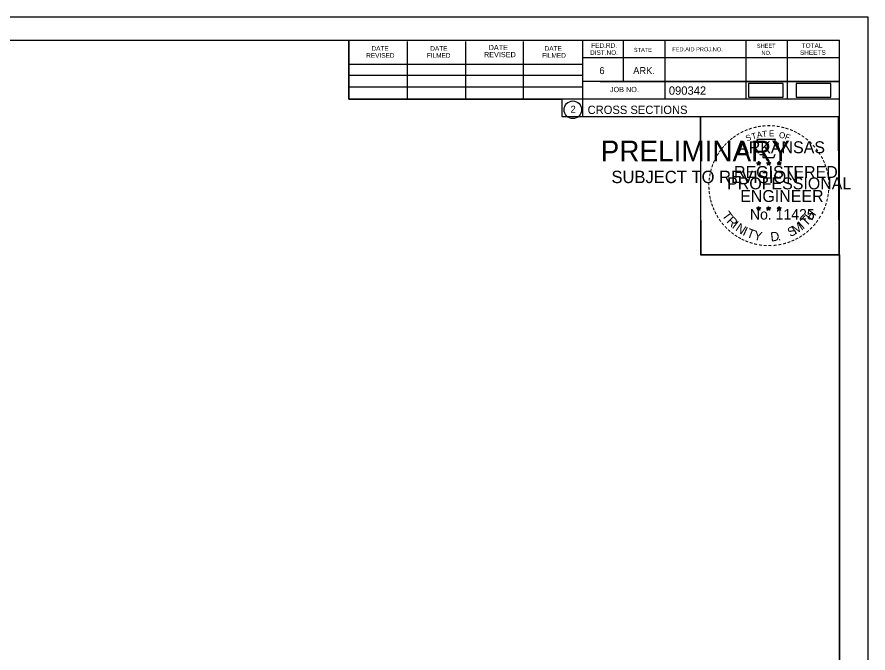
# Model space of a CAD drawing. Extents: x 1370515 to 1370849, y 383299 to 386073.
# Drawn here: x 1370706.1 to 1370848.7, y 385112.8 to 385219.5 of the extents above; entities that cross this region are included whole.
import ezdxf

# ---------------------------------------------------------------- set-up
doc = ezdxf.new("R2010")
doc.units = 0
for name, color, linetype in [('R_Border', 7, 'Continuous'), ('R_Border PE', 7, 'Continuous'), ('R_Border Prem', 7, 'Continuous'), ('R_Detour', 7, 'Continuous'), ('R_No Plot', 7, 'Continuous')]:
    doc.layers.add(name, color=color, linetype=linetype)

msp = doc.modelspace()

# ---------------------------------------------------------------- linework, layer by layer
at = {"layer": 'R_Border'}
for p, q in [((1370527.8, 385215.57), (1370843.98, 385215.57)), ((1370761.72, 385205.69), (1370761.72, 385215.57)), ((1370800.88, 385215.57), (1370800.88, 385202.77)), ((1370807.72, 385215.57), (1370807.72, 385208.63)), ((1370814.66, 385215.57), (1370814.66, 385205.69)), ((1370828.24, 385215.57), (1370828.24, 385205.69)), ((1370835.18, 385215.57), (1370835.18, 385205.69)), ((1370843.98, 385010.11), (1370843.98, 385215.57)), ((1370771.58, 385205.69), (1370771.58, 385215.37)), ((1370781.34, 385205.69), (1370781.34, 385215.37)), ((1370791.02, 385205.69), (1370791.02, 385215.37)), ((1370843.98, 385212.63), (1370800.88, 385212.63)), ((1370843.98, 385212.65), (1370843.98, 385212.65)), ((1370761.72, 385211.55), (1370800.88, 385211.55)), ((1370761.72, 385209.69), (1370800.88, 385209.69)), ((1370843.98, 385208.63), (1370800.88, 385208.63)), ((1370803.84, 385208.63), (1370843.98, 385208.63)), ((1370761.72, 385205.69), (1370761.72, 385207.75)), ((1370761.72, 385207.75), (1370800.88, 385207.75)), ((1370843.98, 385205.69), (1370761.72, 385205.69)), ((1370800.88, 385202.77), (1370843.98, 385202.77))]:
    msp.add_line(p, q, dxfattribs=at)
msp.add_circle((1370799.27, 385203.91), 1.47, dxfattribs=at)
at = {"layer": 'R_Border PE'}
for p, q in [((1370830.07, 385195.03), (1370830.42, 385194.92)), ((1370830.07, 385195.03), (1370830.32, 385194.98)), ((1370830.07, 385195.03), (1370830.3, 385194.91)), ((1370830.2, 385194.62), (1370830.42, 385194.92)), ((1370830.2, 385194.62), (1370830.33, 385194.86)), ((1370830.2, 385194.62), (1370830.41, 385194.84)), ((1370830.42, 385195.28), (1370830.37, 385195.03)), ((1370830.63, 385194.62), (1370830.41, 385194.83)), ((1370830.42, 385194.92), (1370830.42, 385195.28)), ((1370830.42, 385195.28), (1370830.46, 385195.03)), ((1370830.76, 385195.03), (1370830.42, 385194.92)), ((1370830.63, 385194.62), (1370830.42, 385194.92)), ((1370830.76, 385195.03), (1370830.48, 385194.98)), ((1370830.63, 385194.62), (1370830.49, 385194.91)), ((1370830.76, 385195.03), (1370830.56, 385194.93)), ((1370831.74, 385195.03), (1370832.09, 385194.92)), ((1370831.74, 385195.03), (1370831.99, 385194.98)), ((1370831.74, 385195.03), (1370831.97, 385194.91)), ((1370831.87, 385194.62), (1370832.09, 385194.92)), ((1370831.87, 385194.62), (1370832, 385194.86)), ((1370831.87, 385194.62), (1370832.08, 385194.84)), ((1370832.09, 385195.28), (1370832.04, 385195.03)), ((1370832.3, 385194.62), (1370832.08, 385194.83)), ((1370832.09, 385194.92), (1370832.09, 385195.28)), ((1370832.09, 385195.28), (1370832.13, 385195.03)), ((1370832.43, 385195.03), (1370832.09, 385194.92)), ((1370832.3, 385194.62), (1370832.09, 385194.92)), ((1370832.43, 385195.03), (1370832.15, 385194.98)), ((1370832.3, 385194.62), (1370832.16, 385194.91)), ((1370832.43, 385195.03), (1370832.23, 385194.93)), ((1370833.5, 385195.02), (1370833.85, 385194.9)), ((1370833.5, 385195.02), (1370833.75, 385194.97)), ((1370833.5, 385195.02), (1370833.74, 385194.89)), ((1370833.63, 385194.61), (1370833.85, 385194.9)), ((1370833.63, 385194.61), (1370833.76, 385194.85)), ((1370833.63, 385194.61), (1370833.85, 385194.82)), ((1370833.85, 385195.27), (1370833.81, 385195.02)), ((1370833.85, 385194.9), (1370833.85, 385195.27)), ((1370833.85, 385195.27), (1370833.9, 385195.02)), ((1370834.2, 385195.02), (1370833.85, 385194.9)), ((1370834.06, 385194.61), (1370833.85, 385194.9)), ((1370834.06, 385194.61), (1370833.85, 385194.82)), ((1370834.2, 385195.02), (1370833.91, 385194.97)), ((1370834.06, 385194.61), (1370833.93, 385194.9)), ((1370834.2, 385195.02), (1370833.99, 385194.91)), ((1370830.06, 385187.45), (1370830.41, 385187.34)), ((1370830.06, 385187.45), (1370830.32, 385187.41)), ((1370830.06, 385187.45), (1370830.3, 385187.33)), ((1370830.2, 385187.05), (1370830.41, 385187.34)), ((1370830.2, 385187.05), (1370830.32, 385187.29)), ((1370830.2, 385187.05), (1370830.41, 385187.26)), ((1370830.41, 385187.71), (1370830.37, 385187.46)), ((1370830.41, 385187.34), (1370830.41, 385187.71)), ((1370830.41, 385187.71), (1370830.46, 385187.46)), ((1370830.76, 385187.45), (1370830.41, 385187.34)), ((1370830.62, 385187.05), (1370830.41, 385187.34)), ((1370830.62, 385187.05), (1370830.41, 385187.26)), ((1370830.76, 385187.45), (1370830.47, 385187.41)), ((1370830.62, 385187.05), (1370830.49, 385187.34)), ((1370830.76, 385187.45), (1370830.55, 385187.35)), ((1370831.73, 385187.45), (1370832.08, 385187.34)), ((1370831.73, 385187.45), (1370831.98, 385187.41)), ((1370831.73, 385187.45), (1370831.97, 385187.33)), ((1370831.86, 385187.05), (1370832.08, 385187.34)), ((1370831.86, 385187.05), (1370831.99, 385187.29)), ((1370831.86, 385187.05), (1370832.08, 385187.26)), ((1370832.08, 385187.71), (1370832.04, 385187.46)), ((1370832.08, 385187.34), (1370832.08, 385187.71)), ((1370832.08, 385187.71), (1370832.13, 385187.46)), ((1370832.43, 385187.45), (1370832.08, 385187.34)), ((1370832.29, 385187.05), (1370832.08, 385187.34)), ((1370832.29, 385187.05), (1370832.08, 385187.26)), ((1370832.43, 385187.45), (1370832.14, 385187.41)), ((1370832.29, 385187.05), (1370832.16, 385187.34)), ((1370832.43, 385187.45), (1370832.22, 385187.35)), ((1370833.5, 385187.44), (1370833.85, 385187.33)), ((1370833.5, 385187.44), (1370833.75, 385187.4)), ((1370833.5, 385187.44), (1370833.74, 385187.32)), ((1370833.63, 385187.04), (1370833.85, 385187.33)), ((1370833.63, 385187.04), (1370833.76, 385187.28)), ((1370833.63, 385187.04), (1370833.85, 385187.25)), ((1370833.85, 385187.7), (1370833.81, 385187.45)), ((1370833.85, 385187.33), (1370833.85, 385187.7)), ((1370833.85, 385187.7), (1370833.9, 385187.45)), ((1370834.19, 385187.44), (1370833.85, 385187.33)), ((1370834.06, 385187.04), (1370833.85, 385187.33)), ((1370834.06, 385187.04), (1370833.85, 385187.25)), ((1370834.19, 385187.44), (1370833.91, 385187.4)), ((1370834.06, 385187.04), (1370833.92, 385187.33)), ((1370834.19, 385187.44), (1370833.99, 385187.34))]:
    msp.add_line(p, q, dxfattribs=at)
for points in [[(1370830.11, 385198.91), (1370830.38, 385198.08)], [(1370833.62, 385197.98), (1370833.76, 385198.27), (1370833.08, 385198.24), (1370833.22, 385198.91), (1370830.11, 385198.91)], [(1370830.6, 385196.48), (1370830.6, 385196.4), (1370831.16, 385196.38), (1370831.11, 385195.9), (1370832.98, 385195.9), (1370833.18, 385196.44)], [(1370830.42, 385195.28), (1370830.63, 385194.62), (1370830.07, 385195.03), (1370830.76, 385195.03), (1370830.2, 385194.62), (1370830.42, 385195.28)], [(1370832.09, 385195.28), (1370832.3, 385194.62), (1370831.74, 385195.03), (1370832.43, 385195.03), (1370831.87, 385194.62), (1370832.09, 385195.28)], [(1370833.85, 385195.27), (1370834.06, 385194.61), (1370833.5, 385195.02), (1370834.2, 385195.02), (1370833.63, 385194.61), (1370833.85, 385195.27)], [(1370830.41, 385187.71), (1370830.62, 385187.05), (1370830.06, 385187.45), (1370830.76, 385187.45), (1370830.2, 385187.05), (1370830.41, 385187.71)], [(1370832.08, 385187.71), (1370832.29, 385187.05), (1370831.73, 385187.45), (1370832.43, 385187.45), (1370831.86, 385187.05), (1370832.08, 385187.71)], [(1370833.85, 385187.7), (1370834.06, 385187.04), (1370833.5, 385187.44), (1370834.19, 385187.44), (1370833.63, 385187.04), (1370833.85, 385187.7)]]:
    msp.add_lwpolyline(points, dxfattribs=at)
for centre, radius in [((1370830.41, 385194.92), 0.172), ((1370830.41, 385194.92), 0.145), ((1370830.41, 385194.92), 0.116), ((1370830.41, 385194.92), 0.0991), ((1370830.41, 385194.92), 0.0747), ((1370830.41, 385194.92), 0.0495), ((1370830.41, 385194.92), 0.0296), ((1370832.08, 385194.92), 0.172), ((1370832.08, 385194.92), 0.145), ((1370832.08, 385194.92), 0.116), ((1370832.08, 385194.92), 0.0991), ((1370832.08, 385194.92), 0.0747), ((1370832.08, 385194.92), 0.0495), ((1370832.08, 385194.92), 0.0296), ((1370833.85, 385194.9), 0.172), ((1370833.85, 385194.9), 0.145), ((1370833.85, 385194.9), 0.116), ((1370833.85, 385194.9), 0.0991), ((1370833.85, 385194.9), 0.0747), ((1370833.85, 385194.9), 0.0495), ((1370833.85, 385194.9), 0.0296), ((1370830.41, 385187.34), 0.172), ((1370830.41, 385187.34), 0.145), ((1370830.41, 385187.34), 0.116), ((1370830.41, 385187.34), 0.0991), ((1370830.41, 385187.34), 0.0747), ((1370830.41, 385187.34), 0.0495), ((1370830.41, 385187.34), 0.0296), ((1370832.08, 385187.34), 0.172), ((1370832.08, 385187.34), 0.145), ((1370832.08, 385187.34), 0.116), ((1370832.08, 385187.34), 0.0991), ((1370832.08, 385187.34), 0.0747), ((1370832.08, 385187.34), 0.0495), ((1370832.08, 385187.34), 0.0296), ((1370833.85, 385187.33), 0.172), ((1370833.85, 385187.33), 0.145), ((1370833.85, 385187.33), 0.116), ((1370833.85, 385187.33), 0.0991), ((1370833.85, 385187.33), 0.0747), ((1370833.85, 385187.33), 0.0495), ((1370833.85, 385187.33), 0.0296)]:
    msp.add_circle(centre, radius, dxfattribs=at)
at = {"layer": 'R_Detour'}
for points in [[(1370828.7, 385206.01), (1370834.53, 385206.01), (1370834.53, 385208.32), (1370828.7, 385208.32)], [(1370836.7, 385206.01), (1370842.53, 385206.01), (1370842.53, 385208.32), (1370836.7, 385208.32)]]:
    msp.add_lwpolyline(points, close=True, dxfattribs=at)
at = {"layer": 'R_No Plot'}
for p, q in [((1370515.4, 385219.47), (1370848.73, 385219.47)), ((1370820.02, 385180.32), (1370820.02, 385180.32))]:
    msp.add_line(p, q, dxfattribs=at)
for points in [[(1370515.39, 385219.47), (1370848.73, 385219.47), (1370848.73, 385006.13), (1370515.39, 385006.13)], [(1370761.72, 385215.57), (1370761.72, 385205.69), (1370797.45, 385205.69), (1370797.45, 385202.77), (1370820.65, 385202.77), (1370820.65, 385179.56), (1370843.98, 385179.56), (1370843.98, 385010.11), (1370527.8, 385010.11), (1370527.8, 385215.57)], [(1370820.65, 385202.8), (1370843.75, 385202.8), (1370843.87, 385179.56), (1370820.77, 385179.56)]]:
    msp.add_lwpolyline(points, close=True, dxfattribs=at)

# ---------------------------------------------------------------- texts
at = {"layer": 'R_Border'}
for s, height, p in [('DATE', 0.782, (1370765.52, 385213.81)), ('DATE', 0.782, (1370775.38, 385213.81)), ('DATE', 0.879, (1370785.16, 385213.91)), ('DATE', 0.782, (1370794.54, 385213.81)), ('FED.RD.', 0.782, (1370802.36, 385214.29)), ('STATE', 0.684, (1370809.48, 385213.61)), ('FED.AID PROJ.NO.', 0.684, (1370815.94, 385213.71)), ('SHEET', 0.684, (1370830.1, 385214.29)), ('TOTAL', 0.782, (1370837.62, 385214.29)), ('REVISED', 0.782, (1370764.64, 385212.63)), ('FILMED', 0.782, (1370774.8, 385212.63)), ('REVISED', 0.879, (1370784.38, 385212.73)), ('FILMED', 0.782, (1370794.14, 385212.63)), ('DIST.NO.', 0.782, (1370802.16, 385213.11)), ('NO.', 0.684, (1370830.88, 385213.11)), ('SHEETS', 0.782, (1370837.34, 385213.11)), ('6', 1.17, (1370803.72, 385209.89)), ('ARK.', 1.172, (1370809.38, 385209.89)), ('JOB NO.', 0.879, (1370805.48, 385206.87)), ('090342', 1.4, (1370815.36, 385206.43)), ('2', 1.17, (1370798.89, 385203.42)), ('CROSS SECTIONS', 1.4, (1370801.74, 385203.2))]:
    msp.add_text(s, height=height, rotation=360, dxfattribs=at).set_placement(p)
at = {"layer": 'R_Border PE'}
for s, height, rotation, p in [('-', 1.6, 10.2193, (1370830.28, 385200.44)), ('-', 1.6, 5.8968, (1370831.01, 385200.55)), ('-', 1.6, 0.1862, (1370831.78, 385200.62)), ('-', 1.6, 357.743, (1370832.51, 385200.6)), ('-', 1.6, 352.1617, (1370833.25, 385200.55)), ('-', 1.6, 34.0636, (1370826.99, 385199.08)), ('-', 1.6, 28.7918, (1370827.59, 385199.45)), ('-', 1.6, 24.3072, (1370828.22, 385199.76)), ('S', 1, 21.594, (1370828.46, 385198.58)), ('-', 1.6, 19.1761, (1370828.86, 385200.03)), ('T', 1, 16.4036, (1370829.38, 385198.91)), ('-', 1.6, 13.6301, (1370829.61, 385200.27)), ('A', 1, 11.2132, (1370830.2, 385199.17)), ('T', 1, 6.0228, (1370831.05, 385199.33)), ('E', 1, 0.8323, (1370832.16, 385199.44)), ('O', 1, 350.4515, (1370833.76, 385199.23)), ('-', 1.6, 347.2049, (1370833.97, 385200.43)), ('F', 1, 340.0707, (1370834.71, 385199)), ('-', 1.6, 342.3362, (1370834.61, 385200.28)), ('-', 1.6, 337.8551, (1370835.34, 385200.06)), ('-', 1.6, 334.1211, (1370835.97, 385199.79)), ('-', 1.6, 329.6409, (1370836.55, 385199.5)), ('-', 1.6, 48.423, (1370825.06, 385197.41)), ('-', 1.6, 42.9622, (1370825.5, 385197.89)), ('-', 1.6, 38.9507, (1370825.94, 385198.3)), ('-', 1.6, 36.2317, (1370826.41, 385198.68)), ('ARKANSAS', 2, 360, (1370826.96, 385196.62)), ('-', 1.6, 325.8627, (1370837.19, 385199.14)), ('-', 1.6, 320.5297, (1370837.8, 385198.72)), ('-', 1.6, 315.5786, (1370838.4, 385198.23)), ('-', 1.6, 54.2325, (1370824.24, 385196.36)), ('-', 1.6, 50.6142, (1370824.65, 385196.92)), ('-', 1.6, 309.8797, (1370838.97, 385197.68)), ('-', 1.6, 306.6522, (1370839.5, 385197.08)), ('-', 1.6, 67.7743, (1370823.34, 385194.6)), ('-', 1.6, 62.8713, (1370823.6, 385195.21)), ('-', 1.6, 58.0706, (1370823.92, 385195.83)), ('-', 1.4, 303.6753, (1370839.98, 385196.51)), ('-', 1.6, 299.6684, (1370840.3, 385195.9)), ('-', 1.6, 294.6628, (1370840.63, 385195.29)), ('-', 1.6, 75.461, (1370822.93, 385193.26)), ('-', 1.6, 72.3945, (1370823.12, 385193.97)), ('REGISTERED', 2, 360, (1370826.28, 385192.47)), ('DWB', 0.01, 360, (1370830.4, 385194.91)), ('DWB', 0.01, 360, (1370832.07, 385194.91)), ('DWB', 0.01, 360, (1370833.84, 385194.9)), ('-', 1.6, 290.5728, (1370840.88, 385194.71)), ('-', 1.6, 285.1233, (1370841.12, 385194.13)), ('-', 1.6, 81.2013, (1370822.8, 385192.55)), ('PROFESSIONAL', 2, 360, (1370825.13, 385190.56)), ('-', 1.6, 280.5493, (1370841.32, 385193.39)), ('-', 1.6, 276.5962, (1370841.48, 385192.62)), ('-', 1.6, 89.0622, (1370822.69, 385191.15)), ('-', 1.6, 85.1863, (1370822.72, 385191.86)), ('-', 1.6, 274.3301, (1370841.54, 385191.9)), ('-', 1.6, 269.9407, (1370841.57, 385191.27)), ('-', 1.6, 94.1959, (1370822.73, 385190.43)), ('-', 1.6, 98.9479, (1370822.8, 385189.76)), ('ENGINEER', 2, 360, (1370827.32, 385188.44)), ('-', 1.6, 260.9953, (1370841.48, 385189.95)), ('-', 1.6, 263.5172, (1370841.55, 385190.6)), ('-', 1.6, 101.7149, (1370822.94, 385189.03)), ('-', 1.6, 105.4578, (1370823.1, 385188.43)), ('-', 1.6, 255.7626, (1370841.37, 385189.27)), ('-', 1.6, 109.0874, (1370823.31, 385187.8)), ('-', 1.6, 114.0643, (1370823.57, 385187.21)), ('-', 1.6, 115.7288, (1370823.87, 385186.59)), ('T', 1.54, 306.0406, (1370824.17, 385186.18)), ('No. 11425', 1.757, 360, (1370828.95, 385185.49)), ('DWB', 0.01, 360, (1370830.4, 385187.34)), ('DWB', 0.01, 360, (1370832.07, 385187.34)), ('DWB', 0.01, 360, (1370833.83, 385187.33)), ('H', 1.54, 54.6088, (1370839.29, 385185.22)), ('-', 1.6, 244.6197, (1370840.71, 385187.25)), ('-', 1.6, 247.8887, (1370840.97, 385187.88)), ('-', 1.6, 252.8681, (1370841.19, 385188.55)), ('-', 1.6, 120.4471, (1370824.23, 385186)), ('-', 1.6, 125.8934, (1370824.63, 385185.44)), ('R', 1.54, 314.005, (1370824.93, 385185.13)), ('T', 1.54, 46.6444, (1370838.4, 385184.27)), ('-', 1.6, 233.8452, (1370839.91, 385185.84)), ('-', 1.6, 239.0712, (1370840.31, 385186.5)), ('-', 1.6, 130.7181, (1370825.09, 385184.89)), ('-', 1.6, 134.2238, (1370825.61, 385184.35)), ('I', 1.54, 321.9694, (1370825.83, 385184.2)), ('N', 1.54, 326.5002, (1370826.4, 385183.73)), ('I', 1.54, 335.3603, (1370827.61, 385182.94)), ('T', 1.54, 339.8912, (1370828.27, 385182.62)), ('S', 1.54, 26.9312, (1370835.72, 385182.54)), ('M', 1.54, 32.6563, (1370836.56, 385182.95)), ('I', 1.54, 42.1136, (1370837.84, 385183.8)), ('-', 1.6, 225.7653, (1370839, 385184.71)), ('-', 1.6, 231.2538, (1370839.48, 385185.28)), ('-', 1.6, 138.9338, (1370826.14, 385183.88)), ('-', 1.6, 144.6463, (1370826.69, 385183.48)), ('-', 1.6, 148.0898, (1370827.25, 385183.1)), ('-', 1.6, 151.5704, (1370827.83, 385182.78)), ('Y', 1.54, 347.8556, (1370829.49, 385182.17)), ('D', 1.54, 6.3969, (1370832.47, 385181.81)), ('-', 1.6, 212.2491, (1370837.4, 385183.34)), ('-', 1.6, 215.7363, (1370837.93, 385183.73)), ('-', 1.6, 221.0851, (1370838.48, 385184.2)), ('-', 1.6, 154.6002, (1370828.35, 385182.53)), ('-', 1.6, 158.5612, (1370828.98, 385182.28)), ('-', 1.6, 162.7983, (1370829.67, 385182.07)), ('-', 1.6, 167.5555, (1370830.38, 385181.9)), ('-', 1.6, 173.1155, (1370831.15, 385181.79)), ('-', 1.6, 176.5183, (1370831.9, 385181.74)), ('-', 1.6, 181.5918, (1370832.64, 385181.76)), ('-', 1.6, 185.8167, (1370833.45, 385181.83)), ('-', 1.6, 191.2858, (1370834.19, 385181.97)), ('.', 1.54, 13.7642, (1370833.66, 385181.94)), ('-', 1.6, 195.4743, (1370834.92, 385182.16)), ('-', 1.6, 200.7184, (1370835.6, 385182.41)), ('-', 1.6, 204.2516, (1370836.21, 385182.68)), ('-', 1.6, 207.3568, (1370836.84, 385183))]:
    msp.add_text(s, height=height, rotation=rotation, dxfattribs=at).set_placement(p)
at = {"layer": 'R_Border Prem'}
for s, height, p in [('PRELIMINARY', 3.5, (1370803.93, 385195.24)), ('DWB', 0.01, (1370804.68, 385197.08)), ('SUBJECT TO REVISION', 2.0751, (1370805.74, 385191.61))]:
    msp.add_text(s, height=height, rotation=360, dxfattribs=at).set_placement(p)

doc.saveas('drawing.dxf')
